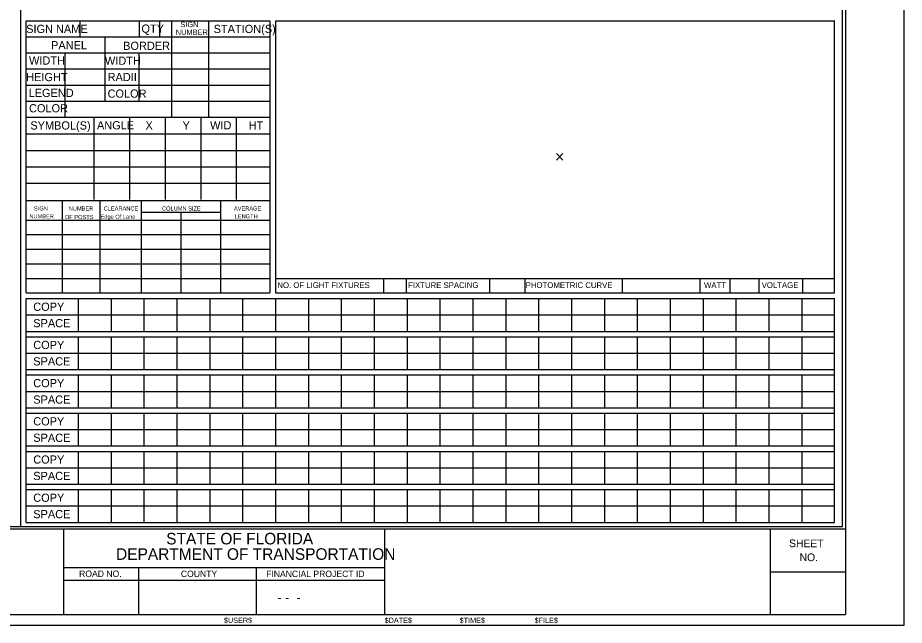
# Model space of a CAD drawing. Extents: x 1374 to 1480, y 568 to 638.
# Drawn here: x 1428.25 to 1456.65, y 568.27 to 587.74 of the extents above; entities that cross this region are included whole.
import ezdxf

# ---------------------------------------------------------------- set-up
doc = ezdxf.new("R2010")
doc.units = 0
for name, color, linetype in [('NonPlottingEle_dp', 7, 'Continuous'), ('PlotBorder_dp', 7, 'Continuous'), ('SheetBorder_dp', 7, 'Continuous'), ('SheetLines_dp', 7, 'Continuous'), ('SheetLinesMisc2_dp', 7, 'Continuous'), ('TextMinor', 7, 'Continuous'), ('TextMisc', 7, 'Continuous')]:
    doc.layers.add(name, color=color, linetype=linetype)

msp = doc.modelspace()

# ---------------------------------------------------------------- linework, layer by layer
at = {"layer": 'NonPlottingEle_dp'}
for p, q in [((1445.51, 583.385), (1445.714, 583.18)), ((1445.51, 583.18), (1445.714, 583.385))]:
    msp.add_line(p, q, dxfattribs=at)
at = {"layer": 'PlotBorder_dp'}
msp.add_lwpolyline([(1400.035, 568.275), (1456.648, 568.275), (1456.648, 604.644), (1400.035, 604.644)], close=True, dxfattribs=at)
at = {"layer": 'SheetBorder_dp'}
for p, q in [((1454.76, 604.301), (1454.76, 568.618)), ((1401.922, 571.363), (1454.76, 571.363)), ((1401.922, 568.618), (1454.76, 568.618))]:
    msp.add_line(p, q, dxfattribs=at)
at = {"layer": 'SheetLines_dp'}
for p, q in [((1429.714, 571.363), (1429.714, 568.618)), ((1440.007, 568.617), (1440.007, 571.362)), ((1452.359, 568.617), (1452.359, 571.362)), ((1429.714, 570.127), (1440.007, 570.127)), ((1432.116, 570.127), (1432.116, 568.618)), ((1435.89, 570.127), (1435.89, 568.618)), ((1452.359, 569.99), (1454.76, 569.99)), ((1429.714, 569.716), (1440.007, 569.716))]:
    msp.add_line(p, q, dxfattribs=at)
at = {"layer": 'SheetLinesMisc2_dp'}
for p, q in [((1428.342, 604.22), (1428.342, 571.444)), ((1454.669, 571.444), (1454.669, 604.22)), ((1428.523, 578.921), (1428.523, 587.644)), ((1428.523, 587.644), (1436.33, 587.644)), ((1430.244, 587.644), (1430.244, 587.129)), ((1432.141, 587.644), (1432.141, 587.129)), ((1432.79, 587.644), (1432.79, 587.129)), ((1433.176, 587.644), (1433.176, 584.553)), ((1434.364, 587.644), (1434.364, 584.553)), ((1436.33, 587.644), (1436.33, 578.921)), ((1436.509, 587.644), (1454.417, 587.644)), ((1436.509, 587.644), (1436.509, 578.934)), ((1454.417, 578.934), (1454.417, 587.645)), ((1428.523, 587.129), (1436.33, 587.129)), ((1431.046, 587.129), (1431.046, 585.062)), ((1428.523, 586.613), (1436.33, 586.613)), ((1429.757, 586.613), (1429.757, 584.553)), ((1432.135, 586.608), (1432.135, 585.062)), ((1428.523, 586.098), (1436.33, 586.098)), ((1428.523, 585.583), (1436.33, 585.583)), ((1428.523, 585.068), (1431.418, 585.068)), ((1431.046, 585.062), (1433.176, 585.062)), ((1433.176, 585.068), (1436.33, 585.068)), ((1428.523, 584.553), (1436.33, 584.553)), ((1430.691, 584.542), (1430.691, 581.912)), ((1431.832, 584.542), (1431.832, 581.912)), ((1432.972, 584.542), (1432.972, 581.912)), ((1434.113, 584.542), (1434.113, 581.912)), ((1435.254, 584.542), (1435.254, 581.912)), ((1428.524, 584.016), (1436.33, 584.016)), ((1428.524, 583.49), (1436.33, 583.49)), ((1428.524, 582.964), (1436.33, 582.964)), ((1428.524, 582.438), (1436.33, 582.438)), ((1428.523, 581.887), (1436.33, 581.887)), ((1429.681, 581.887), (1429.681, 578.921)), ((1430.879, 581.887), (1430.879, 578.921)), ((1432.201, 581.887), (1432.201, 578.921)), ((1434.747, 581.887), (1434.747, 578.921)), ((1428.523, 581.258), (1436.33, 581.258)), ((1432.201, 581.51), (1434.745, 581.51)), ((1433.479, 581.51), (1433.479, 578.921)), ((1428.523, 580.791), (1436.33, 580.791)), ((1428.523, 580.323), (1436.33, 580.323)), ((1428.523, 579.856), (1436.33, 579.856)), ((1428.523, 579.388), (1436.33, 579.388)), ((1436.509, 579.389), (1454.417, 579.389)), ((1439.968, 579.389), (1439.968, 578.921)), ((1440.693, 579.389), (1440.693, 578.921)), ((1443.359, 579.389), (1443.359, 578.921)), ((1444.494, 579.389), (1444.494, 578.921)), ((1447.612, 579.389), (1447.612, 578.921)), ((1450.101, 579.389), (1450.101, 578.921)), ((1451.062, 579.389), (1451.062, 578.921)), ((1451.988, 579.389), (1451.988, 578.921)), ((1453.383, 579.389), (1453.383, 578.921)), ((1428.522, 578.742), (1454.417, 578.742)), ((1428.522, 571.572), (1428.522, 578.742)), ((1428.523, 578.921), (1436.33, 578.921)), ((1430.189, 578.742), (1430.189, 577.69)), ((1431.243, 578.742), (1431.243, 577.69)), ((1432.296, 578.742), (1432.296, 577.69)), ((1433.349, 578.742), (1433.349, 577.69)), ((1434.403, 578.742), (1434.403, 577.69)), ((1435.456, 578.742), (1435.456, 577.69)), ((1436.509, 578.934), (1436.509, 578.922)), ((1436.509, 578.921), (1454.417, 578.921)), ((1436.509, 578.742), (1436.509, 577.69)), ((1437.563, 578.742), (1437.563, 577.69)), ((1438.616, 578.742), (1438.616, 577.69)), ((1439.67, 578.742), (1439.67, 577.69)), ((1440.723, 578.742), (1440.723, 577.69)), ((1441.776, 578.742), (1441.776, 577.69)), ((1442.83, 578.742), (1442.83, 577.69)), ((1443.883, 578.742), (1443.883, 577.69)), ((1444.937, 578.742), (1444.937, 577.69)), ((1445.99, 578.742), (1445.99, 577.69)), ((1447.043, 578.742), (1447.043, 577.69)), ((1448.097, 578.742), (1448.097, 577.69)), ((1449.15, 578.742), (1449.15, 577.69)), ((1450.203, 578.742), (1450.203, 577.69)), ((1451.257, 578.742), (1451.257, 577.69)), ((1452.31, 578.742), (1452.31, 577.69)), ((1453.364, 578.742), (1453.364, 577.69)), ((1454.417, 578.922), (1454.417, 578.934)), ((1454.417, 571.572), (1454.417, 578.742)), ((1428.522, 578.216), (1454.417, 578.216)), ((1428.522, 577.69), (1454.417, 577.69)), ((1428.522, 577.518), (1454.417, 577.518)), ((1430.189, 577.518), (1430.189, 576.466)), ((1431.243, 577.518), (1431.243, 576.466)), ((1432.296, 577.518), (1432.296, 576.466)), ((1433.349, 577.518), (1433.349, 576.466)), ((1434.403, 577.518), (1434.403, 576.466)), ((1435.456, 577.518), (1435.456, 576.466)), ((1436.509, 577.518), (1436.509, 576.466)), ((1437.563, 577.518), (1437.563, 576.466)), ((1438.616, 577.518), (1438.616, 576.466)), ((1439.67, 577.518), (1439.67, 576.466)), ((1440.723, 577.518), (1440.723, 576.466)), ((1441.776, 577.518), (1441.776, 576.466)), ((1442.83, 577.518), (1442.83, 576.466)), ((1443.883, 577.518), (1443.883, 576.466)), ((1444.937, 577.518), (1444.937, 576.466)), ((1445.99, 577.518), (1445.99, 576.466)), ((1447.043, 577.518), (1447.043, 576.466)), ((1448.097, 577.518), (1448.097, 576.466)), ((1449.15, 577.518), (1449.15, 576.466)), ((1450.203, 577.518), (1450.203, 576.466)), ((1451.257, 577.518), (1451.257, 576.466)), ((1452.31, 577.518), (1452.31, 576.466)), ((1453.364, 577.518), (1453.364, 576.466)), ((1428.522, 576.992), (1454.417, 576.992)), ((1428.522, 576.466), (1454.417, 576.466)), ((1428.522, 576.294), (1454.417, 576.294)), ((1430.189, 576.294), (1430.189, 575.242)), ((1431.243, 576.294), (1431.243, 575.242)), ((1432.296, 576.294), (1432.296, 575.242)), ((1433.349, 576.294), (1433.349, 575.242)), ((1434.403, 576.294), (1434.403, 575.242)), ((1435.456, 576.294), (1435.456, 575.242)), ((1436.509, 576.294), (1436.509, 575.242)), ((1437.563, 576.294), (1437.563, 575.242)), ((1438.616, 576.294), (1438.616, 575.242)), ((1439.67, 576.294), (1439.67, 575.242)), ((1440.723, 576.294), (1440.723, 575.242)), ((1441.776, 576.294), (1441.776, 575.242)), ((1442.83, 576.294), (1442.83, 575.242)), ((1443.883, 576.294), (1443.883, 575.242)), ((1444.937, 576.294), (1444.937, 575.242)), ((1445.99, 576.294), (1445.99, 575.242)), ((1447.043, 576.294), (1447.043, 575.242)), ((1448.097, 576.294), (1448.097, 575.242)), ((1449.15, 576.294), (1449.15, 575.242)), ((1450.203, 576.294), (1450.203, 575.242)), ((1451.257, 576.294), (1451.257, 575.242)), ((1452.31, 576.294), (1452.31, 575.242)), ((1453.364, 576.294), (1453.364, 575.242)), ((1428.522, 575.768), (1454.417, 575.768)), ((1428.522, 575.242), (1454.417, 575.242)), ((1428.522, 575.071), (1454.417, 575.071)), ((1430.189, 575.071), (1430.189, 574.019)), ((1431.243, 575.071), (1431.243, 574.019)), ((1432.296, 575.071), (1432.296, 574.019)), ((1433.349, 575.071), (1433.349, 574.019)), ((1434.403, 575.071), (1434.403, 574.019)), ((1435.456, 575.071), (1435.456, 574.019)), ((1436.509, 575.071), (1436.509, 574.019)), ((1437.563, 575.071), (1437.563, 574.019)), ((1438.616, 575.071), (1438.616, 574.019)), ((1439.67, 575.071), (1439.67, 574.019)), ((1440.723, 575.071), (1440.723, 574.019)), ((1441.776, 575.071), (1441.776, 574.019)), ((1442.83, 575.071), (1442.83, 574.019)), ((1443.883, 575.071), (1443.883, 574.019)), ((1444.937, 575.071), (1444.937, 574.019)), ((1445.99, 575.071), (1445.99, 574.019)), ((1447.043, 575.071), (1447.043, 574.019)), ((1448.097, 575.071), (1448.097, 574.019)), ((1449.15, 575.071), (1449.15, 574.019)), ((1450.203, 575.071), (1450.203, 574.019)), ((1451.257, 575.071), (1451.257, 574.019)), ((1452.31, 575.071), (1452.31, 574.019)), ((1453.364, 575.071), (1453.364, 574.019)), ((1428.522, 574.545), (1454.417, 574.545)), ((1428.522, 574.019), (1454.417, 574.019)), ((1428.522, 573.847), (1454.417, 573.847)), ((1430.189, 573.847), (1430.189, 572.795)), ((1431.243, 573.847), (1431.243, 572.795)), ((1432.296, 573.847), (1432.296, 572.795)), ((1433.349, 573.847), (1433.349, 572.795)), ((1434.403, 573.847), (1434.403, 572.795)), ((1435.456, 573.847), (1435.456, 572.795)), ((1436.509, 573.847), (1436.509, 572.795)), ((1437.563, 573.847), (1437.563, 572.795)), ((1438.616, 573.847), (1438.616, 572.795)), ((1439.67, 573.847), (1439.67, 572.795)), ((1440.723, 573.847), (1440.723, 572.795)), ((1441.776, 573.847), (1441.776, 572.795)), ((1442.83, 573.847), (1442.83, 572.795)), ((1443.883, 573.847), (1443.883, 572.795)), ((1444.937, 573.847), (1444.937, 572.795)), ((1445.99, 573.847), (1445.99, 572.795)), ((1447.043, 573.847), (1447.043, 572.795)), ((1448.097, 573.847), (1448.097, 572.795)), ((1449.15, 573.847), (1449.15, 572.795)), ((1450.203, 573.847), (1450.203, 572.795)), ((1451.257, 573.847), (1451.257, 572.795)), ((1452.31, 573.847), (1452.31, 572.795)), ((1453.364, 573.847), (1453.364, 572.795)), ((1428.522, 573.321), (1454.417, 573.321)), ((1428.522, 572.795), (1454.417, 572.795)), ((1428.522, 572.623), (1454.417, 572.623)), ((1430.189, 572.623), (1430.189, 571.572)), ((1431.243, 572.623), (1431.243, 571.572)), ((1432.296, 572.623), (1432.296, 571.572)), ((1433.349, 572.623), (1433.349, 571.572)), ((1434.403, 572.623), (1434.403, 571.572)), ((1435.456, 572.623), (1435.456, 571.572)), ((1436.509, 572.623), (1436.509, 571.572)), ((1437.563, 572.623), (1437.563, 571.572)), ((1438.616, 572.623), (1438.616, 571.572)), ((1439.67, 572.623), (1439.67, 571.572)), ((1440.723, 572.623), (1440.723, 571.572)), ((1441.776, 572.623), (1441.776, 571.572)), ((1442.83, 572.623), (1442.83, 571.572)), ((1443.883, 572.623), (1443.883, 571.572)), ((1444.937, 572.623), (1444.937, 571.572)), ((1445.99, 572.623), (1445.99, 571.572)), ((1447.043, 572.623), (1447.043, 571.572)), ((1448.097, 572.623), (1448.097, 571.572)), ((1449.15, 572.623), (1449.15, 571.572)), ((1450.203, 572.623), (1450.203, 571.572)), ((1451.257, 572.623), (1451.257, 571.572)), ((1452.31, 572.623), (1452.31, 571.572)), ((1453.364, 572.623), (1453.364, 571.572)), ((1428.522, 572.097), (1454.417, 572.097)), ((1402.016, 571.444), (1454.669, 571.444)), ((1428.522, 571.572), (1454.417, 571.572))]:
    msp.add_line(p, q, dxfattribs=at)

# ---------------------------------------------------------------- texts
at = {"layer": 'TextMinor'}
for s, height, p in [('SIGN NAME', 0.2625, (1428.523, 587.249)), ('QTY', 0.2625, (1432.216, 587.258)), ('SIGN', 0.1716, (1433.463, 587.437)), ('STATION(S)', 0.2625, (1434.528, 587.248)), ('NUMBER', 0.1716, (1433.314, 587.188)), ('PANEL', 0.2625, (1429.321, 586.726)), ('BORDER', 0.2625, (1431.629, 586.708)), ('WIDTH', 0.2625, (1428.615, 586.236)), ('WIDTH', 0.2625, (1431.046, 586.23)), ('HEIGHT', 0.2625, (1428.523, 585.707)), ('RADII', 0.2625, (1431.132, 585.708)), ('LEGEND', 0.2625, (1428.602, 585.198)), ('COLOR', 0.2625, (1431.13, 585.176)), ('COLOR', 0.2625, (1428.615, 584.706)), ('SYMBOL(S)', 0.2625, (1428.657, 584.156)), ('ANGLE', 0.2625, (1430.791, 584.161)), ('X', 0.262, (1432.345, 584.156)), ('Y', 0.262, (1433.531, 584.156)), ('WID', 0.2625, (1434.414, 584.161)), ('HT', 0.2625, (1435.651, 584.156)), ('SIGN', 0.1312, (1428.773, 581.563)), ('NUMBER', 0.1312, (1429.887, 581.561)), ('CLEARANCE', 0.1312, (1431.005, 581.562)), ('COLUMN SIZE', 0.13124, (1432.875, 581.562)), ('AVERAGE', 0.1312, (1435.177, 581.562)), ('NUMBER', 0.1312, (1428.626, 581.313)), ('OF POSTS', 0.1312, (1429.763, 581.289)), ('Edge Of Lane', 0.13124, (1430.904, 581.298)), ('LENGTH', 0.1312, (1435.202, 581.313)), ('NO. OF LIGHT FIXTURES', 0.18601, (1436.569, 579.078)), ('FIXTURE SPACING', 0.18601, (1440.757, 579.078)), ('PHOTOMETRIC CURVE', 0.18601, (1444.524, 579.078)), ('WATT', 0.186, (1450.234, 579.078)), ('VOLTAGE', 0.186, (1452.081, 579.078)), ('COPY', 0.2625, (1428.75, 578.348)), ('SPACE', 0.2625, (1428.75, 577.822)), ('COPY', 0.2625, (1428.75, 577.124)), ('SPACE', 0.2625, (1428.75, 576.598)), ('COPY', 0.2625, (1428.75, 575.901)), ('SPACE', 0.2625, (1428.75, 575.375)), ('COPY', 0.2625, (1428.75, 574.677)), ('SPACE', 0.2625, (1428.75, 574.151)), ('COPY', 0.2625, (1428.75, 573.453)), ('SPACE', 0.2625, (1428.75, 572.927)), ('COPY', 0.2625, (1428.75, 572.23)), ('SPACE', 0.2625, (1428.75, 571.704)), ('$USER$', 0.1681, (1434.857, 568.35)), ('$DATE$', 0.1681, (1440.004, 568.35)), ('$TIME$', 0.1681, (1442.405, 568.35)), ('$FILE$', 0.1681, (1444.807, 568.35))]:
    msp.add_text(s, height=height, dxfattribs=at).set_placement(p)
at = {"layer": 'TextMisc'}
for s, height, p in [('STATE OF FLORIDA', 0.37056, (1433.008, 570.865)), ('DEPARTMENT OF TRANSPORTATION', 0.37056, (1431.402, 570.371)), ('ROAD NO.', 0.2059, (1430.219, 569.822)), ('COUNTY', 0.2059, (1433.478, 569.818)), ('FINANCIAL PROJECT ID', 0.20587, (1436.209, 569.818)), ('      - -  -  ', 0.30194, (1435.897, 569.019))]:
    msp.add_text(s, height=height, dxfattribs=at).set_placement(p)
for s, p in [('SHEET', (1452.959, 570.776)), ('NO.', (1453.296, 570.33))]:
    msp.add_text(s, height=0.247, rotation=359.8607, dxfattribs=at).set_placement(p)

doc.saveas('drawing.dxf')
